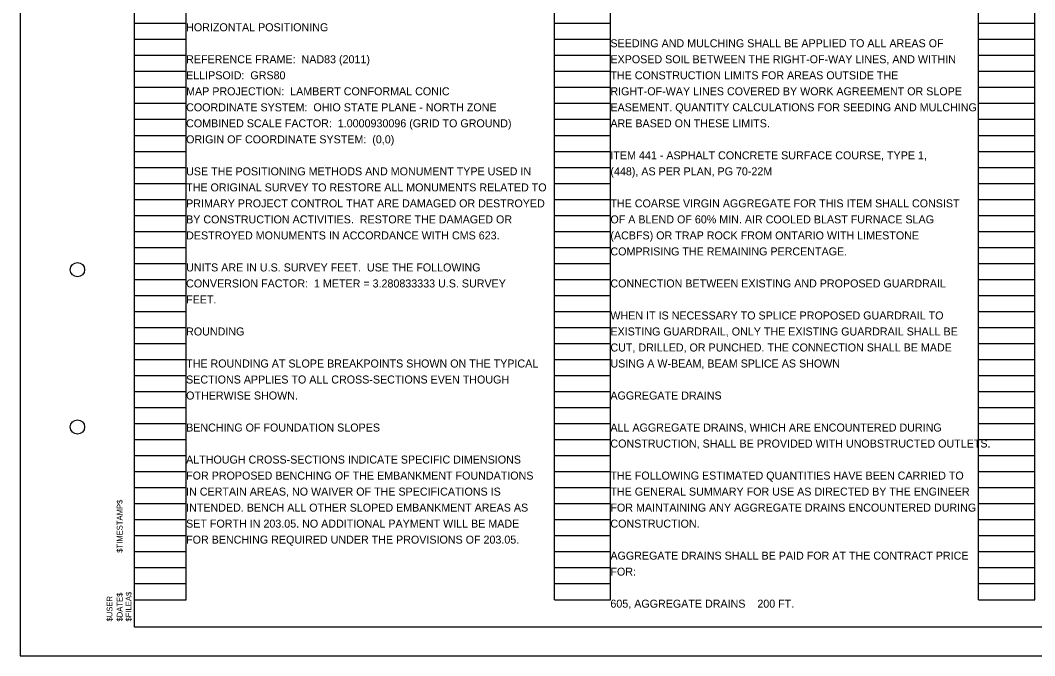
# Model space of a CAD drawing. Extents: x 0 to 41.8, y 0 to 22.
# Drawn here: x 0 to 17.74, y 0 to 11.11 of the extents above; entities that cross this region are included whole.
import ezdxf

# ---------------------------------------------------------------- set-up
doc = ezdxf.new("R2010")
doc.units = 0
for name, color, linetype in [('SC_Scratch1', 7, 'Continuous'), ('SH_Border', 7, 'Continuous'), ('SH_Cut_Line', 7, 'Continuous'), ('SH_Data', 7, 'Continuous'), ('SH_Text', 7, 'Continuous')]:
    doc.layers.add(name, color=color, linetype=linetype)

msp = doc.modelspace()

# ---------------------------------------------------------------- linework, layer by layer
at = {"layer": 'SC_Scratch1'}
for p, q in [((2, 0.98), (2, 21.14)), ((2.9, 0.98), (2.9, 21.14)), ((9.34, 0.98), (9.34, 21.14)), ((10.32, 0.98), (10.32, 21.14)), ((16.76, 0.98), (16.76, 21.14)), ((17.74, 0.98), (17.74, 21.14)), ((2, 11.06), (2.9, 11.06)), ((9.34, 11.06), (10.32, 11.06)), ((16.76, 11.06), (17.74, 11.06)), ((2, 10.78), (2.9, 10.78)), ((9.34, 10.78), (10.32, 10.78)), ((16.76, 10.78), (17.74, 10.78)), ((2, 10.5), (2.9, 10.5)), ((9.34, 10.5), (10.32, 10.5)), ((16.76, 10.5), (17.74, 10.5)), ((2, 10.22), (2.9, 10.22)), ((9.34, 10.22), (10.32, 10.22)), ((16.76, 10.22), (17.74, 10.22)), ((2, 9.94), (2.9, 9.94)), ((9.34, 9.94), (10.32, 9.94)), ((16.76, 9.94), (17.74, 9.94)), ((2, 9.66), (2.9, 9.66)), ((9.34, 9.66), (10.32, 9.66)), ((16.76, 9.66), (17.74, 9.66)), ((2, 9.38), (2.9, 9.38)), ((9.34, 9.38), (10.32, 9.38)), ((16.76, 9.38), (17.74, 9.38)), ((2, 9.1), (2.9, 9.1)), ((9.34, 9.1), (10.32, 9.1)), ((16.76, 9.1), (17.74, 9.1)), ((2, 8.82), (2.9, 8.82)), ((9.34, 8.82), (10.32, 8.82)), ((16.76, 8.82), (17.74, 8.82)), ((2, 8.54), (2.9, 8.54)), ((9.34, 8.54), (10.32, 8.54)), ((16.76, 8.54), (17.74, 8.54)), ((2, 8.26), (2.9, 8.26)), ((9.34, 8.26), (10.32, 8.26)), ((16.76, 8.26), (17.74, 8.26)), ((2, 7.98), (2.9, 7.98)), ((9.34, 7.98), (10.32, 7.98)), ((16.76, 7.98), (17.74, 7.98)), ((2, 7.7), (2.9, 7.7)), ((9.34, 7.7), (10.32, 7.7)), ((16.76, 7.7), (17.74, 7.7)), ((2, 7.42), (2.9, 7.42)), ((9.34, 7.42), (10.32, 7.42)), ((16.76, 7.42), (17.74, 7.42)), ((2, 7.14), (2.9, 7.14)), ((9.34, 7.14), (10.32, 7.14)), ((16.76, 7.14), (17.74, 7.14)), ((2, 6.86), (2.9, 6.86)), ((9.34, 6.86), (10.32, 6.86)), ((16.76, 6.86), (17.74, 6.86)), ((2, 6.58), (2.9, 6.58)), ((9.34, 6.58), (10.32, 6.58)), ((16.76, 6.58), (17.74, 6.58)), ((2, 6.3), (2.9, 6.3)), ((9.34, 6.3), (10.32, 6.3)), ((16.76, 6.3), (17.74, 6.3)), ((2, 6.02), (2.9, 6.02)), ((9.34, 6.02), (10.32, 6.02)), ((16.76, 6.02), (17.74, 6.02)), ((2, 5.74), (2.9, 5.74)), ((9.34, 5.74), (10.32, 5.74)), ((16.76, 5.74), (17.74, 5.74)), ((2, 5.46), (2.9, 5.46)), ((9.34, 5.46), (10.32, 5.46)), ((16.76, 5.46), (17.74, 5.46)), ((2, 5.18), (2.9, 5.18)), ((9.34, 5.18), (10.32, 5.18)), ((16.76, 5.18), (17.74, 5.18)), ((2, 4.9), (2.9, 4.9)), ((9.34, 4.9), (10.32, 4.9)), ((16.76, 4.9), (17.74, 4.9)), ((2, 4.62), (2.9, 4.62)), ((9.34, 4.62), (10.32, 4.62)), ((16.76, 4.62), (17.74, 4.62)), ((2, 4.34), (2.9, 4.34)), ((9.34, 4.34), (10.32, 4.34)), ((16.76, 4.34), (17.74, 4.34)), ((2, 4.06), (2.9, 4.06)), ((9.34, 4.06), (10.32, 4.06)), ((16.76, 4.06), (17.74, 4.06)), ((2, 3.78), (2.9, 3.78)), ((9.34, 3.78), (10.32, 3.78)), ((16.76, 3.78), (17.74, 3.78)), ((2, 3.5), (2.9, 3.5)), ((9.34, 3.5), (10.32, 3.5)), ((16.76, 3.5), (17.74, 3.5)), ((2, 3.22), (2.9, 3.22)), ((9.34, 3.22), (10.32, 3.22)), ((16.76, 3.22), (17.74, 3.22)), ((2, 2.94), (2.9, 2.94)), ((9.34, 2.94), (10.32, 2.94)), ((16.76, 2.94), (17.74, 2.94)), ((2, 2.66), (2.9, 2.66)), ((9.34, 2.66), (10.32, 2.66)), ((16.76, 2.66), (17.74, 2.66)), ((2, 2.38), (2.9, 2.38)), ((9.34, 2.38), (10.32, 2.38)), ((16.76, 2.38), (17.74, 2.38)), ((2, 2.1), (2.9, 2.1)), ((9.34, 2.1), (10.32, 2.1)), ((16.76, 2.1), (17.74, 2.1)), ((2, 1.82), (2.9, 1.82)), ((9.34, 1.82), (10.32, 1.82)), ((16.76, 1.82), (17.74, 1.82)), ((2, 1.54), (2.9, 1.54)), ((9.34, 1.54), (10.32, 1.54)), ((16.76, 1.54), (17.74, 1.54)), ((2, 1.26), (2.9, 1.26)), ((9.34, 1.26), (10.32, 1.26)), ((16.76, 1.26), (17.74, 1.26)), ((2, 0.98), (2.9, 0.98)), ((9.34, 0.98), (10.32, 0.98)), ((16.76, 0.98), (17.74, 0.98)), ((0, 0), (0, 0))]:
    msp.add_line(p, q, dxfattribs=at)
at = {"layer": 'SH_Border'}
msp.add_lwpolyline([(2, 21.5), (33.5, 21.5), (33.5, 0.5), (2, 0.5)], close=True, dxfattribs=at)
for centre in [(1, 6.75), (1, 4)]:
    msp.add_circle(centre, 0.125, dxfattribs=at)
at = {"layer": 'SH_Cut_Line'}
msp.add_lwpolyline([(0, 0), (34, 0), (34, 22), (0, 22)], close=True, dxfattribs=at)

# ---------------------------------------------------------------- texts
at = {"layer": 'SH_Data'}
for s, p in [('$TIMESTAMP$', (1.788, 1.8)), ('$DATE$', (1.788, 0.598)), ('$FILEA$', (1.944, 0.598)), ('$USER', (1.611, 0.598))]:
    msp.add_text(s, height=0.1, rotation=89.9931, dxfattribs=at).set_placement(p)
at = {"layer": 'SH_Text'}
for s, p in [('HORIZONTAL POSITIONING', (2.9, 10.92)), ('SEEDING AND MULCHING SHALL BE APPLIED TO ALL AREAS OF ', (10.32, 10.64)), ('REFERENCE FRAME:  NAD83 (2011)', (2.9, 10.36)), ('EXPOSED SOIL BETWEEN THE RIGHT-OF-WAY LINES, AND WITHIN ', (10.32, 10.36)), ('ELLIPSOID:  GRS80', (2.9, 10.08)), ('THE CONSTRUCTION LIMITS FOR AREAS OUTSIDE THE ', (10.32, 10.08)), ('MAP PROJECTION:  LAMBERT CONFORMAL CONIC', (2.9, 9.8)), ('RIGHT-OF-WAY LINES COVERED BY WORK AGREEMENT OR SLOPE ', (10.32, 9.8)), ('COORDINATE SYSTEM:  OHIO STATE PLANE - NORTH ZONE', (2.9, 9.52)), ('EASEMENT. QUANTITY CALCULATIONS FOR SEEDING AND MULCHING ', (10.32, 9.52)), ('COMBINED SCALE FACTOR:  1.0000930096 (GRID TO GROUND)', (2.9, 9.24)), ('ARE BASED ON THESE LIMITS.', (10.32, 9.24)), ('ORIGIN OF COORDINATE SYSTEM:  (0,0)', (2.9, 8.96)), ('ITEM 441 - ASPHALT CONCRETE SURFACE COURSE, TYPE 1, ', (10.32, 8.68)), ('USE THE POSITIONING METHODS AND MONUMENT TYPE USED IN ', (2.9, 8.4)), ('(448), AS PER PLAN, PG 70-22M', (10.32, 8.4)), ('THE ORIGINAL SURVEY TO RESTORE ALL MONUMENTS RELATED TO ', (2.9, 8.12)), ('PRIMARY PROJECT CONTROL THAT ARE DAMAGED OR DESTROYED ', (2.9, 7.84)), ('THE COARSE VIRGIN AGGREGATE FOR THIS ITEM SHALL CONSIST ', (10.32, 7.84)), ('BY CONSTRUCTION ACTIVITIES.  RESTORE THE DAMAGED OR ', (2.9, 7.56)), ('OF A BLEND OF 60% MIN. AIR COOLED BLAST FURNACE SLAG ', (10.32, 7.56)), ('DESTROYED MONUMENTS IN ACCORDANCE WITH CMS 623.', (2.9, 7.28)), ('(ACBFS) OR TRAP ROCK FROM ONTARIO WITH LIMESTONE ', (10.32, 7.28)), ('COMPRISING THE REMAINING PERCENTAGE.', (10.32, 7)), ('UNITS ARE IN U.S. SURVEY FEET.  USE THE FOLLOWING ', (2.9, 6.72)), ('CONVERSION FACTOR:  1 METER = 3.280833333 U.S. SURVEY ', (2.9, 6.44)), ('CONNECTION BETWEEN EXISTING AND PROPOSED GUARDRAIL', (10.32, 6.44)), ('FEET.', (2.9, 6.16)), ('WHEN IT IS NECESSARY TO SPLICE PROPOSED GUARDRAIL TO ', (10.32, 5.88)), ('ROUNDING', (2.9, 5.6)), ('EXISTING GUARDRAIL, ONLY THE EXISTING GUARDRAIL SHALL BE ', (10.32, 5.6)), ('CUT, DRILLED, OR PUNCHED. THE CONNECTION SHALL BE MADE ', (10.32, 5.32)), ('THE ROUNDING AT SLOPE BREAKPOINTS SHOWN ON THE TYPICAL ', (2.9, 5.04)), ('USING A W-BEAM, BEAM SPLICE AS SHOWN', (10.32, 5.04)), ('SECTIONS APPLIES TO ALL CROSS-SECTIONS EVEN THOUGH ', (2.9, 4.76)), ('OTHERWISE SHOWN.', (2.9, 4.48)), ('AGGREGATE DRAINS', (10.32, 4.48)), ('BENCHING OF FOUNDATION SLOPES', (2.9, 3.92)), ('ALL AGGREGATE DRAINS, WHICH ARE ENCOUNTERED DURING ', (10.32, 3.92)), ('CONSTRUCTION, SHALL BE PROVIDED WITH UNOBSTRUCTED OUTLETS.', (10.32, 3.64)), ('ALTHOUGH CROSS-SECTIONS INDICATE SPECIFIC DIMENSIONS ', (2.9, 3.36)), ('FOR PROPOSED BENCHING OF THE EMBANKMENT FOUNDATIONS ', (2.9, 3.08)), ('THE FOLLOWING ESTIMATED QUANTITIES HAVE BEEN CARRIED TO ', (10.32, 3.08)), ('IN CERTAIN AREAS, NO WAIVER OF THE SPECIFICATIONS IS ', (2.9, 2.8)), ('THE GENERAL SUMMARY FOR USE AS DIRECTED BY THE ENGINEER ', (10.32, 2.8)), ('INTENDED. BENCH ALL OTHER SLOPED EMBANKMENT AREAS AS ', (2.9, 2.52)), ('FOR MAINTAINING ANY AGGREGATE DRAINS ENCOUNTERED DURING ', (10.32, 2.52)), ('SET FORTH IN 203.05. NO ADDITIONAL PAYMENT WILL BE MADE ', (2.9, 2.24)), ('CONSTRUCTION. ', (10.32, 2.24)), ('FOR BENCHING REQUIRED UNDER THE PROVISIONS OF 203.05.', (2.9, 1.96)), ('AGGREGATE DRAINS SHALL BE PAID FOR AT THE CONTRACT PRICE ', (10.32, 1.68)), ('FOR:', (10.32, 1.4)), ('605, AGGREGATE DRAINS    200 FT.', (10.32, 0.84))]:
    msp.add_text(s, height=0.14, dxfattribs=at).set_placement(p)

doc.saveas('drawing.dxf')
